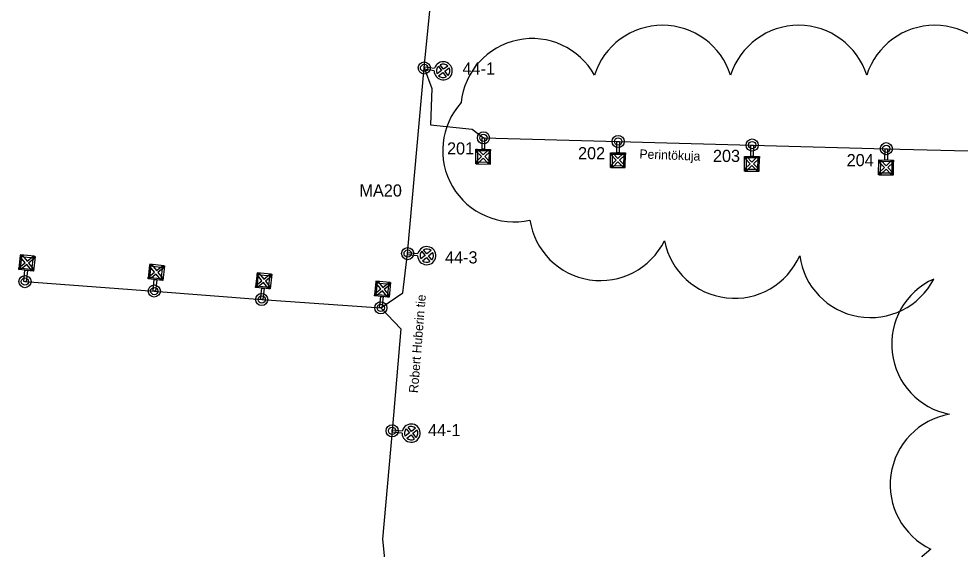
# Model space of a CAD drawing. Extents: x 25497851 to 25498523, y 6686544 to 6687372.
# Drawn here: x 25497851.1 to 25498083.9, y 6687075.9 to 6687207 of the extents above; entities that cross this region are included whole.
import ezdxf

# ---------------------------------------------------------------- set-up
doc = ezdxf.new("R2010")
doc.units = 0
for name, color, linetype in [('KAAPELI', 7, 'Continuous'), ('KEYGWT_ANNOTATION', 7, 'Continuous'), ('MUU_SUUNNITELMAVIIVA', 7, 'Continuous'), ('PYLVAS', 7, 'Continuous'), ('TEKSTI_SUUNNITELMA-ALUE', 7, 'Continuous'), ('VALAISIN', 7, 'Continuous')]:
    doc.layers.add(name, color=color, linetype=linetype)

msp = doc.modelspace()

# ---------------------------------------------------------------- linework, layer by layer
at = {"layer": 'KAAPELI'}
for p, q in [((25497951.39, 6687194.86), (25497955.43, 6687236.8)), ((25497947.28, 6687148.96), (25497951.39, 6687194.86)), ((25497966.01, 6687177.58), (25497999.33, 6687176.69)), ((25497999.33, 6687176.69), (25498032.46, 6687175.8)), ((25498032.46, 6687175.8), (25498065.63, 6687174.9)), ((25498065.63, 6687174.9), (25498098.74, 6687174.02)), ((25497852.66, 6687142.04), (25497884.63, 6687139.71)), ((25497884.63, 6687139.71), (25497911.19, 6687137.62)), ((25497911.19, 6687137.62), (25497940.63, 6687135.56))]:
    msp.add_line(p, q, dxfattribs=at)
for points in [[(25497951.39, 6687194.86), (25497953.29, 6687189.79), (25497952.93, 6687180.8), (25497963.22, 6687179.71), (25497966.01, 6687177.58)], [(25497940.63, 6687135.56), (25497946.1, 6687139.25), (25497947.28, 6687148.96)], [(25497940.63, 6687135.56), (25497945.62, 6687130.39), (25497943.46, 6687105.16)], [(25497943.45, 6687105.13), (25497941.06, 6687078.34), (25497942.59, 6687062.85)]]:
    msp.add_lwpolyline(points, dxfattribs=at)
at = {"layer": 'MUU_SUUNNITELMAVIIVA'}
for centre, radius, start, end in [((25498010.3, 6687187.75), 17.65, 17.5, 162.5), ((25498043.96, 6687187.75), 17.65, 17.5, 162.5), ((25498077.61, 6687187.75), 17.65, 17.5, 162.5), ((25497978.05, 6687184.48), 17.65, 29.0783, 174.0783), ((25497973.58, 6687174.46), 17.64, 137.8628, 282.8628), ((25497994.95, 6687159.95), 17.65, 188.7788, 333.7788), ((25498028.09, 6687155.57), 17.65, 191.1505, 336.1505), ((25498061.71, 6687150.78), 17.64, 187.6385, 332.6385), ((25498084.61, 6687126.57), 17.65, 114.169, 259.169), ((25498084.24, 6687091.83), 17.65, 99.6368, 244.6368), ((25498087.01, 6687061.58), 17.65, 125.8219, 270.8219)]:
    msp.add_arc(centre, radius, start, end, dxfattribs=at)
at = {"layer": 'PYLVAS'}
for centre, radius in [((25497951.39, 6687194.86), 1.5), ((25497951.39, 6687194.86), 0.9), ((25497966.01, 6687177.58), 1.5), ((25497966.01, 6687177.58), 0.9), ((25497999.33, 6687176.69), 1.5), ((25497999.33, 6687176.69), 0.9), ((25498032.46, 6687175.8), 1.5), ((25498032.46, 6687175.8), 0.9), ((25498065.63, 6687174.9), 1.5), ((25498065.63, 6687174.9), 0.9), ((25497947.28, 6687148.96), 1.5), ((25497947.28, 6687148.96), 0.9), ((25497852.66, 6687142.04), 1.5), ((25497852.66, 6687142.04), 0.9), ((25497884.63, 6687139.71), 1.5), ((25497884.63, 6687139.71), 0.9), ((25497911.19, 6687137.62), 1.5), ((25497911.19, 6687137.62), 0.9), ((25497940.63, 6687135.56), 1.5), ((25497940.63, 6687135.56), 0.9), ((25497943.45, 6687105.13), 1.5), ((25497943.45, 6687105.13), 0.9)]:
    msp.add_circle(centre, radius, dxfattribs=at)
at = {"layer": 'VALAISIN'}
for p, q in [((25497951.34, 6687194.56), (25497951.43, 6687195.16)), ((25497953.82, 6687194.18), (25497951.34, 6687194.56)), ((25497951.43, 6687195.16), (25497953.91, 6687194.77)), ((25497954.87, 6687195.27), (25497955.65, 6687194.2)), ((25497956.14, 6687194.56), (25497955.35, 6687195.63)), ((25497957.2, 6687195.34), (25497956.14, 6687194.56)), ((25497956.49, 6687194.08), (25497957.56, 6687194.86)), ((25497955.65, 6687194.2), (25497954.59, 6687193.42)), ((25497954.94, 6687192.94), (25497956.01, 6687193.72)), ((25497956.01, 6687193.72), (25497956.79, 6687192.65)), ((25497957.27, 6687193.01), (25497956.49, 6687194.08)), ((25497947.25, 6687148.66), (25497947.31, 6687149.26)), ((25497949.75, 6687148.4), (25497947.25, 6687148.66)), ((25497947.31, 6687149.26), (25497949.81, 6687148.99)), ((25497951.57, 6687148.51), (25497950.55, 6687147.68)), ((25497950.74, 6687149.54), (25497951.57, 6687148.51)), ((25497950.92, 6687147.21), (25497951.95, 6687148.04)), ((25497952.04, 6687148.88), (25497951.21, 6687149.91)), ((25497951.95, 6687148.04), (25497952.78, 6687147.01)), ((25497953.07, 6687149.72), (25497952.04, 6687148.88)), ((25497952.42, 6687148.42), (25497953.45, 6687149.25)), ((25497953.25, 6687147.39), (25497952.42, 6687148.42)), ((25497948.21, 6687105.01), (25497947.39, 6687106.04)), ((25497949.24, 6687105.83), (25497948.21, 6687105.01)), ((25497943.42, 6687104.83), (25497943.48, 6687105.43)), ((25497945.91, 6687104.54), (25497943.42, 6687104.83)), ((25497943.48, 6687105.43), (25497945.98, 6687105.14)), ((25497947.74, 6687104.63), (25497946.7, 6687103.81)), ((25497946.92, 6687105.67), (25497947.74, 6687104.63)), ((25497947.07, 6687103.34), (25497948.11, 6687104.16)), ((25497948.11, 6687104.16), (25497948.93, 6687103.13)), ((25497948.58, 6687104.54), (25497949.62, 6687105.36)), ((25497949.4, 6687103.5), (25497948.58, 6687104.54))]:
    msp.add_line(p, q, dxfattribs=at)
for points in [[(25497966.31, 6687177.57), (25497966.27, 6687174.76), (25497965.67, 6687174.77), (25497965.71, 6687177.58)], [(25497999.63, 6687176.69), (25497999.6, 6687173.88), (25497999, 6687173.88), (25497999.03, 6687176.7)], [(25498032.76, 6687175.8), (25498032.73, 6687172.99), (25498032.13, 6687172.99), (25498032.16, 6687175.81)], [(25497964.55, 6687174.78), (25497964.51, 6687171.13), (25497964.11, 6687171.14), (25497964.15, 6687174.78)], [(25497964.69, 6687174.65), (25497965.96, 6687173.36), (25497967.25, 6687174.63), (25497967.67, 6687174.62), (25497967.67, 6687174.2), (25497966.38, 6687172.93), (25497967.64, 6687171.64), (25497967.64, 6687171.22), (25497967.21, 6687171.22), (25497965.95, 6687172.52), (25497964.65, 6687171.25), (25497964.23, 6687171.26), (25497964.24, 6687171.68), (25497965.53, 6687172.94), (25497964.26, 6687174.23), (25497964.27, 6687174.66)], [(25497967.8, 6687174.74), (25497967.79, 6687174.34), (25497964.26, 6687174.38), (25497964.27, 6687174.78)], [(25497967.76, 6687171.22), (25497967.8, 6687174.62), (25497967.4, 6687174.62), (25497967.36, 6687171.22)], [(25497997.87, 6687173.9), (25497997.83, 6687170.25), (25497997.43, 6687170.25), (25497997.47, 6687173.9)], [(25497998.02, 6687173.77), (25497999.28, 6687172.48), (25498000.57, 6687173.74), (25498001, 6687173.74), (25498000.99, 6687173.31), (25497999.7, 6687172.05), (25498000.96, 6687170.76), (25498000.96, 6687170.34), (25498000.53, 6687170.34), (25497999.27, 6687171.63), (25497997.98, 6687170.37), (25497997.55, 6687170.37), (25497997.56, 6687170.8), (25497998.85, 6687172.06), (25497997.59, 6687173.35), (25497997.59, 6687173.78)], [(25498001.12, 6687173.86), (25498001.12, 6687173.46), (25497997.59, 6687173.5), (25497997.59, 6687173.9)], [(25498001.08, 6687170.34), (25498001.12, 6687173.74), (25498000.72, 6687173.74), (25498000.68, 6687170.34)], [(25498065.93, 6687174.9), (25498065.9, 6687172.08), (25498065.3, 6687172.09), (25498065.33, 6687174.9)], [(25497964.23, 6687171.54), (25497964.23, 6687171.14), (25497967.76, 6687171.1), (25497967.76, 6687171.5)], [(25498031, 6687173.01), (25498030.96, 6687169.36), (25498030.56, 6687169.36), (25498030.6, 6687173.01)], [(25498031.14, 6687172.88), (25498032.41, 6687171.59), (25498033.7, 6687172.85), (25498034.13, 6687172.85), (25498034.12, 6687172.43), (25498032.83, 6687171.16), (25498034.09, 6687169.87), (25498034.09, 6687169.45), (25498033.66, 6687169.45), (25498032.4, 6687170.74), (25498031.11, 6687169.48), (25498030.68, 6687169.49), (25498030.69, 6687169.91), (25498031.98, 6687171.17), (25498030.71, 6687172.46), (25498030.72, 6687172.89)], [(25498034.25, 6687172.97), (25498034.24, 6687172.57), (25498030.72, 6687172.61), (25498030.72, 6687173.01)], [(25498034.21, 6687169.45), (25498034.25, 6687172.85), (25498033.85, 6687172.85), (25498033.81, 6687169.45)], [(25498064.18, 6687172.1), (25498064.14, 6687168.46), (25498063.74, 6687168.46), (25498063.78, 6687172.11)], [(25498064.32, 6687171.98), (25498065.59, 6687170.69), (25498066.88, 6687171.95), (25498067.3, 6687171.94), (25498067.3, 6687171.52), (25498066.01, 6687170.26), (25498067.27, 6687168.97), (25498067.27, 6687168.54), (25498066.84, 6687168.55), (25498065.58, 6687169.84), (25498064.28, 6687168.58), (25498063.86, 6687168.58), (25498063.86, 6687169.01), (25498065.16, 6687170.27), (25498063.89, 6687171.56), (25498063.9, 6687171.98)], [(25498067.43, 6687172.07), (25498067.42, 6687171.67), (25498063.89, 6687171.71), (25498063.9, 6687172.11)], [(25498067.39, 6687168.54), (25498067.43, 6687171.94), (25498067.03, 6687171.95), (25498066.99, 6687168.55)], [(25497997.56, 6687170.65), (25497997.55, 6687170.25), (25498001.08, 6687170.21), (25498001.08, 6687170.61)], [(25498030.68, 6687169.76), (25498030.68, 6687169.36), (25498034.21, 6687169.32), (25498034.21, 6687169.72)], [(25498063.86, 6687168.86), (25498063.86, 6687168.46), (25498067.39, 6687168.42), (25498067.39, 6687168.82)], [(25497851.51, 6687148.54), (25497851.15, 6687145.16), (25497851.55, 6687145.11), (25497851.91, 6687148.5)], [(25497854.24, 6687144.83), (25497853.1, 6687146.23), (25497851.7, 6687145.1), (25497851.28, 6687145.14), (25497851.32, 6687145.57), (25497852.73, 6687146.7), (25497851.59, 6687148.1), (25497851.63, 6687148.53), (25497852.05, 6687148.48), (25497853.19, 6687147.08), (25497854.6, 6687148.21), (25497855.02, 6687148.17), (25497854.97, 6687147.75), (25497853.57, 6687146.61), (25497854.71, 6687145.21), (25497854.66, 6687144.79)], [(25497854.99, 6687147.89), (25497855.03, 6687148.29), (25497851.52, 6687148.66), (25497851.48, 6687148.26)], [(25497854.37, 6687144.69), (25497854.75, 6687148.32), (25497855.15, 6687148.28), (25497854.77, 6687144.65)], [(25497851.14, 6687145.04), (25497851.18, 6687145.43), (25497854.69, 6687145.06), (25497854.65, 6687144.66)], [(25497883.49, 6687146.21), (25497883.13, 6687142.83), (25497883.53, 6687142.78), (25497883.88, 6687146.17)], [(25497886.22, 6687142.5), (25497885.08, 6687143.9), (25497883.67, 6687142.77), (25497883.25, 6687142.81), (25497883.3, 6687143.23), (25497884.7, 6687144.37), (25497883.56, 6687145.77), (25497883.61, 6687146.2), (25497884.03, 6687146.15), (25497885.17, 6687144.75), (25497886.57, 6687145.88), (25497887, 6687145.84), (25497886.95, 6687145.42), (25497885.55, 6687144.28), (25497886.68, 6687142.88), (25497886.64, 6687142.46)], [(25497886.97, 6687145.56), (25497887.01, 6687145.96), (25497883.5, 6687146.33), (25497883.46, 6687145.93)], [(25497886.35, 6687142.36), (25497886.73, 6687145.99), (25497887.13, 6687145.95), (25497886.75, 6687142.32)], [(25497852.36, 6687142.08), (25497852.66, 6687144.88), (25497853.25, 6687144.81), (25497852.96, 6687142.01)], [(25497883.12, 6687142.7), (25497883.16, 6687143.1), (25497886.67, 6687142.73), (25497886.63, 6687142.33)], [(25497910.04, 6687144.11), (25497909.69, 6687140.73), (25497910.08, 6687140.69), (25497910.44, 6687144.07)], [(25497912.77, 6687140.4), (25497911.64, 6687141.81), (25497910.23, 6687140.67), (25497909.81, 6687140.71), (25497909.85, 6687141.14), (25497911.26, 6687142.27), (25497910.12, 6687143.68), (25497910.16, 6687144.1), (25497910.59, 6687144.05), (25497911.72, 6687142.65), (25497913.13, 6687143.78), (25497913.55, 6687143.74), (25497913.51, 6687143.32), (25497912.1, 6687142.18), (25497913.24, 6687140.78), (25497913.2, 6687140.36)], [(25497913.52, 6687143.46), (25497913.57, 6687143.86), (25497910.06, 6687144.23), (25497910.01, 6687143.83)], [(25497912.9, 6687140.26), (25497913.29, 6687143.89), (25497913.69, 6687143.85), (25497913.3, 6687140.22)], [(25497884.34, 6687139.75), (25497884.63, 6687142.54), (25497885.23, 6687142.48), (25497884.93, 6687139.68)], [(25497909.67, 6687140.61), (25497909.72, 6687141), (25497913.22, 6687140.63), (25497913.18, 6687140.24)], [(25497939.44, 6687142.05), (25497939.11, 6687138.66), (25497939.5, 6687138.62), (25497939.84, 6687142.01)], [(25497942.19, 6687138.36), (25497941.05, 6687139.75), (25497939.65, 6687138.61), (25497939.23, 6687138.65), (25497939.27, 6687139.07), (25497940.67, 6687140.22), (25497939.52, 6687141.61), (25497939.56, 6687142.03), (25497939.98, 6687141.99), (25497941.13, 6687140.6), (25497942.53, 6687141.74), (25497942.95, 6687141.7), (25497942.91, 6687141.28), (25497941.51, 6687140.13), (25497942.66, 6687138.74), (25497942.62, 6687138.32)], [(25497942.92, 6687141.42), (25497942.96, 6687141.82), (25497939.45, 6687142.17), (25497939.41, 6687141.77)], [(25497942.33, 6687138.22), (25497942.68, 6687141.85), (25497943.08, 6687141.81), (25497942.72, 6687138.18)], [(25497910.89, 6687137.65), (25497911.19, 6687140.45), (25497911.78, 6687140.38), (25497911.49, 6687137.58)], [(25497939.09, 6687138.54), (25497939.13, 6687138.94), (25497942.64, 6687138.59), (25497942.6, 6687138.19)], [(25497940.33, 6687135.59), (25497940.61, 6687138.39), (25497941.21, 6687138.33), (25497940.93, 6687135.53)]]:
    msp.add_lwpolyline(points, close=True, dxfattribs=at)
for centre, radius, start, end in [((25497956.07, 6687194.14), 2.25, 351.2726, 163.6103), ((25497956.07, 6687194.14), 1.65, 171.2726, 205.7969), ((25497956.07, 6687194.14), 1.65, 136.7482, 171.2726), ((25497956.07, 6687194.14), 1.65, 46.7482, 115.7969), ((25497956.07, 6687194.14), 1.65, 351.2726, 25.7969), ((25497956.07, 6687194.14), 2.25, 178.9348, 351.2726), ((25497956.07, 6687194.14), 1.65, 226.7482, 295.7969), ((25497956.07, 6687194.14), 1.65, 316.7482, 351.2726), ((25497952, 6687148.46), 2.25, 353.991, 166.3287), ((25497952, 6687148.46), 1.65, 49.4667, 118.5153), ((25497952, 6687148.46), 2.25, 181.6533, 353.991), ((25497952, 6687148.46), 1.65, 173.991, 208.5153), ((25497952, 6687148.46), 1.65, 139.4667, 173.991), ((25497952, 6687148.46), 1.65, 319.4667, 353.991), ((25497952, 6687148.46), 1.65, 353.991, 28.5153), ((25497952, 6687148.46), 1.65, 229.4667, 298.5153), ((25497948.16, 6687104.58), 2.25, 353.4004, 165.7381), ((25497948.16, 6687104.58), 1.65, 48.876, 117.9247), ((25497948.16, 6687104.58), 2.25, 181.0626, 353.4004), ((25497948.16, 6687104.58), 1.65, 173.4004, 207.9247), ((25497948.16, 6687104.58), 1.65, 138.876, 173.4004), ((25497948.16, 6687104.58), 1.65, 318.876, 353.4004), ((25497948.16, 6687104.58), 1.65, 353.4004, 27.9247), ((25497948.16, 6687104.58), 1.65, 228.876, 297.9247)]:
    msp.add_arc(centre, radius, start, end, dxfattribs=at)

# ---------------------------------------------------------------- texts
at = {"layer": 'KEYGWT_ANNOTATION'}
for s, p in [('44-1', (25497960.84, 6687193.23)), ('MA20', (25497935.37, 6687163.08)), ('44-3', (25497956.53, 6687146.54)), ('44-1', (25497952.33, 6687103.83))]:
    msp.add_text(s, height=3, dxfattribs=at).set_placement(p)
at = {"layer": 'TEKSTI_SUUNNITELMA-ALUE'}
for s, p in [('201', (25497957.02, 6687173.47)), ('202', (25497989.41, 6687172.29)), ('203', (25498022.77, 6687171.62)), ('204', (25498055.83, 6687170.58))]:
    msp.add_text(s, height=3, dxfattribs=at).set_placement(p)
for s, rotation, p in [('Perintökuja', 357.849, (25498004.56, 6687172.49)), ('Robert Huberin tie', 85.3437, (25497949.81, 6687114.42))]:
    msp.add_text(s, height=2.25, rotation=rotation, dxfattribs=at).set_placement(p)

doc.saveas('drawing.dxf')
